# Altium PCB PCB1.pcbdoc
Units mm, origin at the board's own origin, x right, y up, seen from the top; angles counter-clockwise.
Board outline 128.65 x 93 mm, 2 copper layers (Top Layer, Bottom Layer), stack 1.58 mm thick; 4 components, 0 nets, 0 pads, 0 vias.
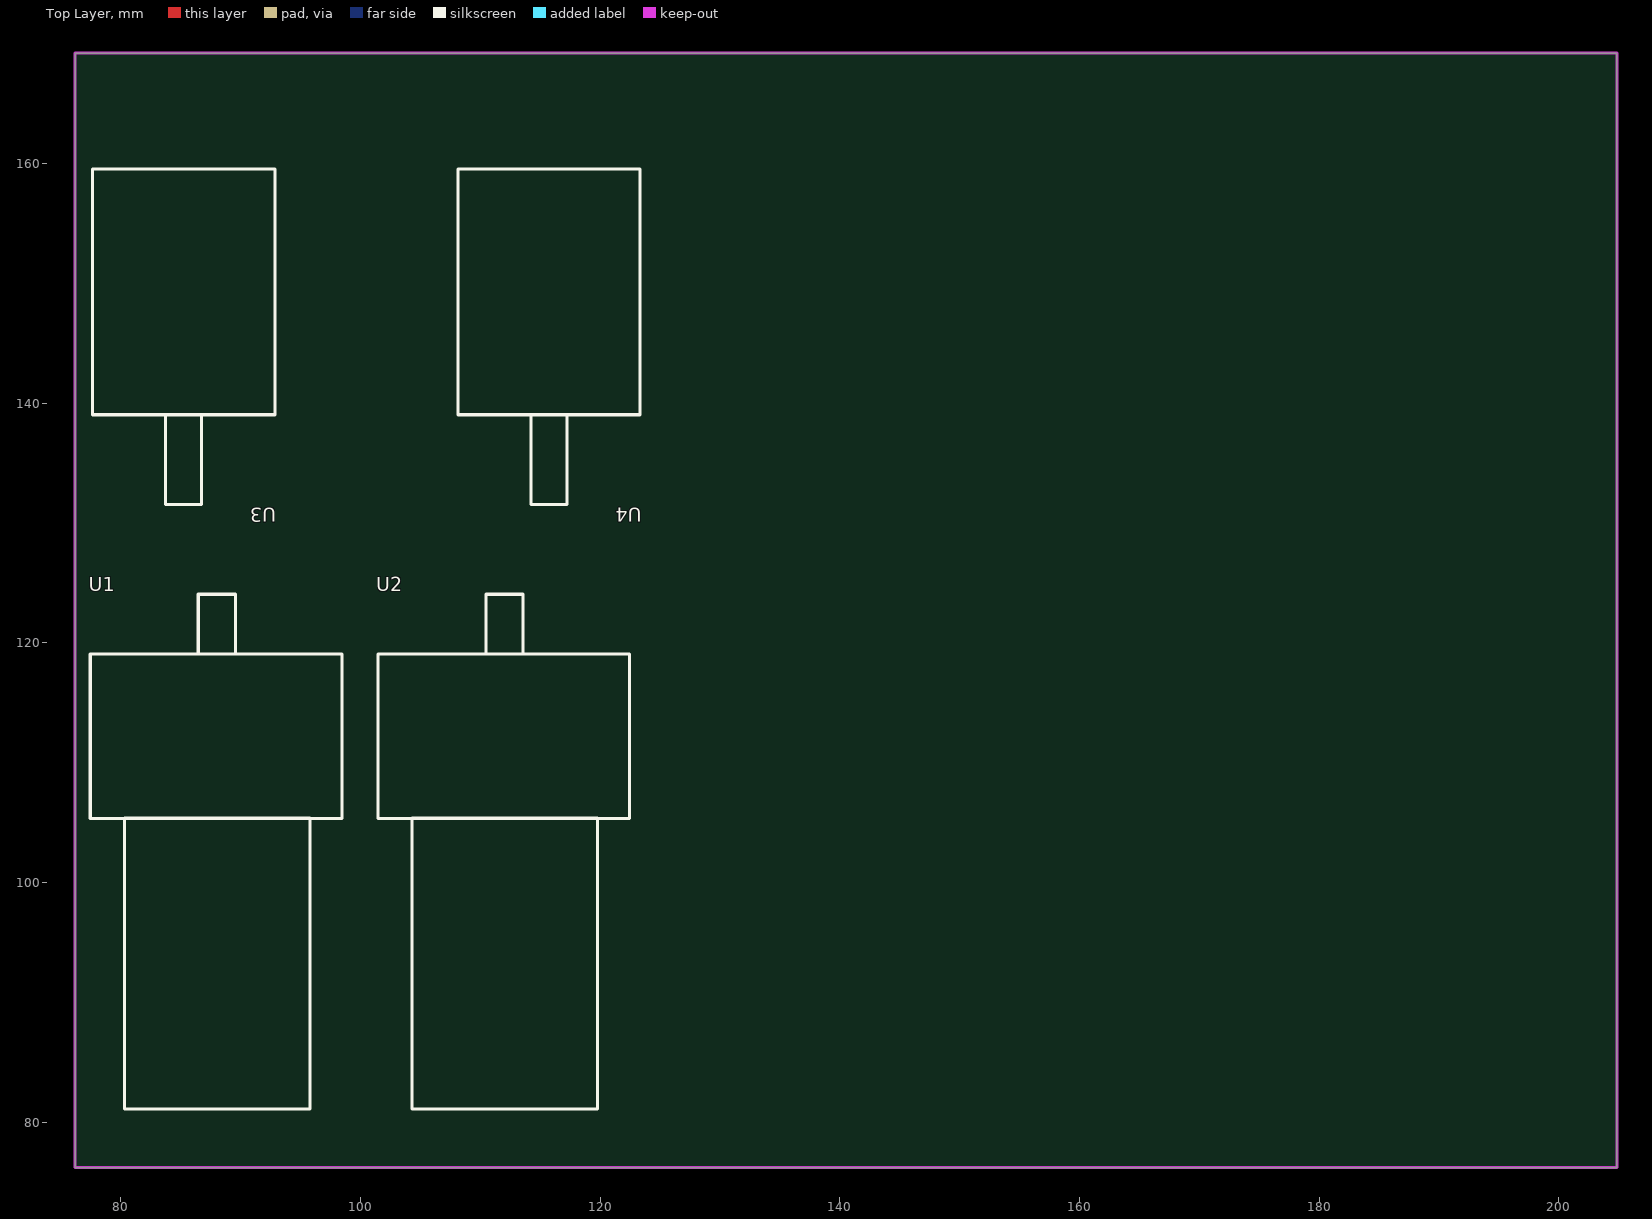
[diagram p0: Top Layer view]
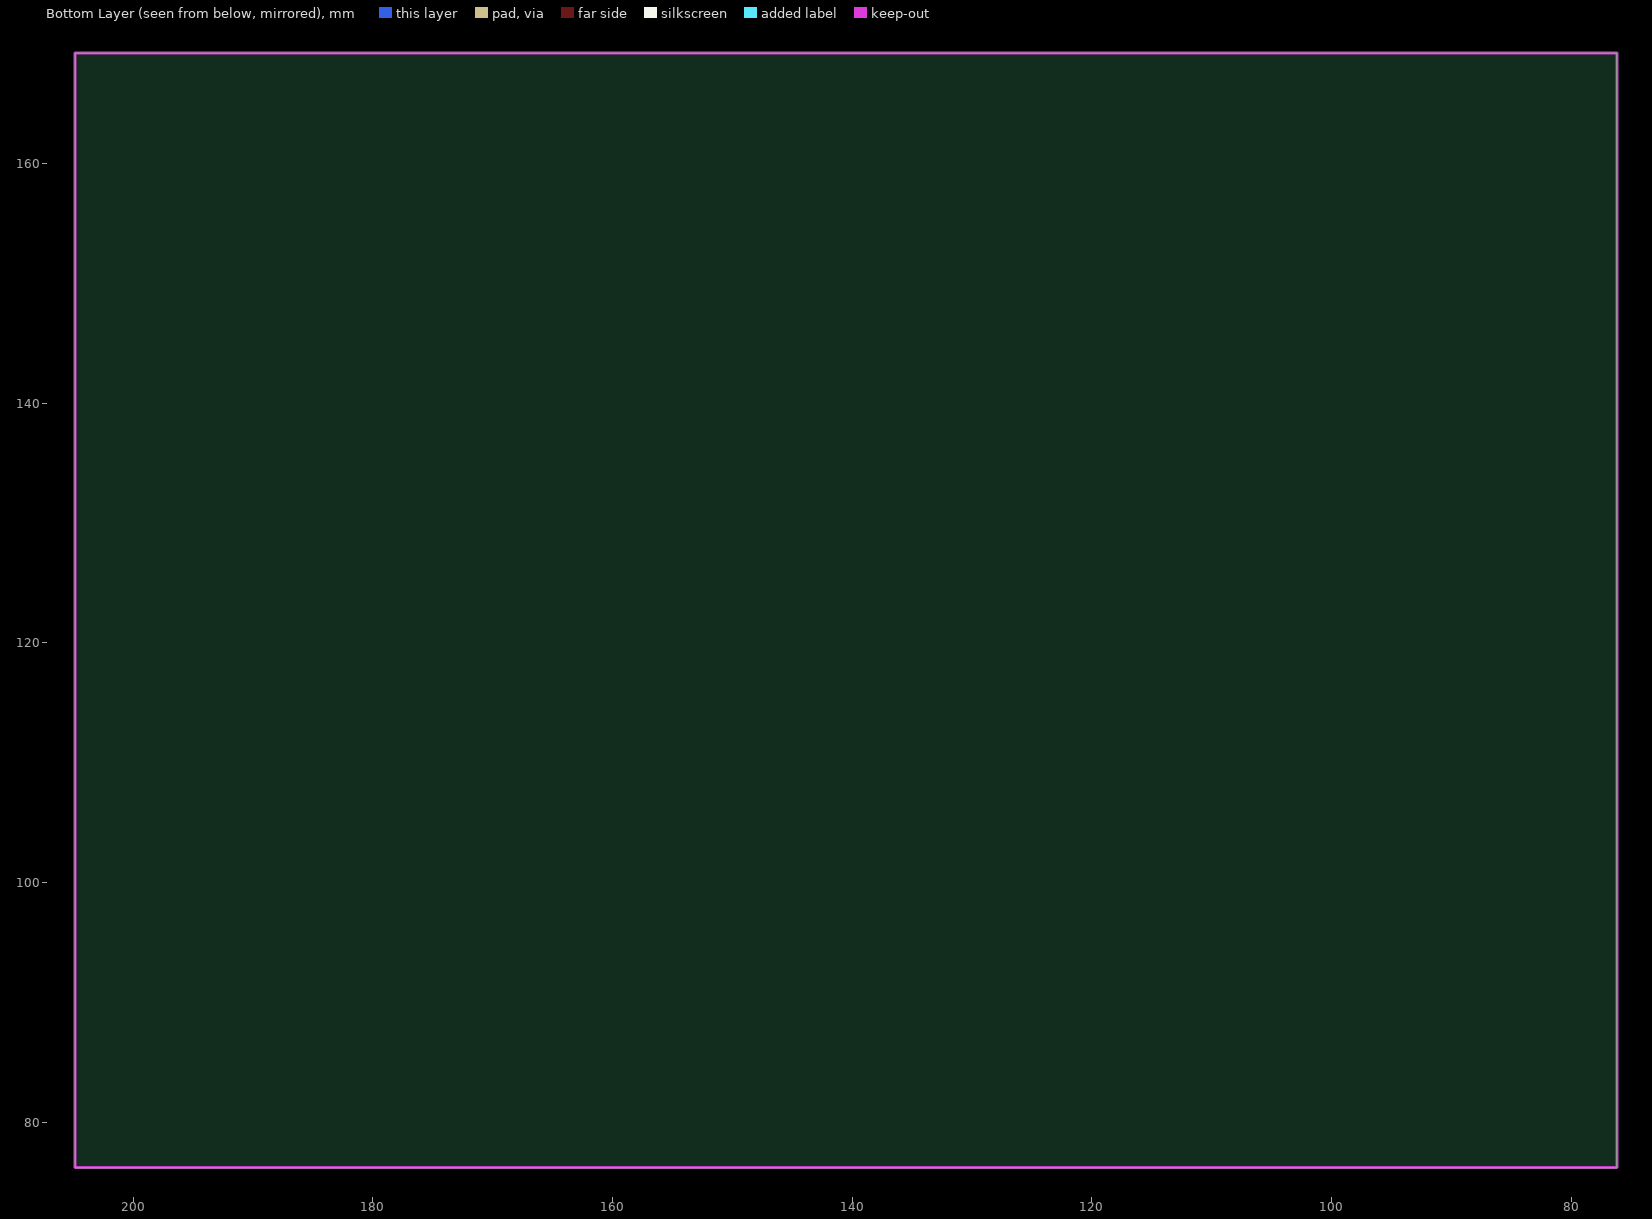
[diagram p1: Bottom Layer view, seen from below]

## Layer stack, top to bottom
Top Solder Mask Layer: solder mask 0.0102, Dk 3.3
Top Layer: signal copper 0.0356
Dielectric1: surface 1.5088, FR4, Dk 4.5
Bottom Layer: signal copper 0.0356
Bottom Solder Mask Layer: solder mask 0.0102, Dk 3.3

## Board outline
76.2,169.2 204.851,169.2 204.851,76.2 76.2,76.2

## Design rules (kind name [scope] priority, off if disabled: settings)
BoardOutlineClearance copperThickness1oz [All] p0: genericclearance=0.254 ignorepadtopadclearanceinfootprint=FALSE except(0: Arc-SplitContinuation Track-SplitContinuation SMDPad-SplitContinuation THPad-SplitContinuation Via-SplitContinuation Fill-SplitContinuation Poly-SplitContinuation Region-SplitContinuation Text-SplitContinuation)
BoardOutlineClearance copperThickness2oz [All] p0: genericclearance=0.254 ignorepadtopadclearanceinfootprint=FALSE except(0: Arc-SplitContinuation Track-SplitContinuation SMDPad-SplitContinuation THPad-SplitContinuation Via-SplitContinuation Fill-SplitContinuation Poly-SplitContinuation Region-SplitContinuation Text-SplitContinuation)
BoardOutlineClearance otherClearance [All] p0: genericclearance=0.254 ignorepadtopadclearanceinfootprint=FALSE except(0: Arc-SplitContinuation Track-SplitContinuation SMDPad-SplitContinuation THPad-SplitContinuation Via-SplitContinuation Fill-SplitContinuation Poly-SplitContinuation Region-SplitContinuation Text-SplitContinuation)
Clearance copperThickness1oz [All] p1: gap=0.178 ignorepadtopadclearanceinfootprint=FALSE
Clearance copperThickness2oz [All] p1: gap=0.178 ignorepadtopadclearanceinfootprint=FALSE
Clearance otherClearance [All] p1: gap=0.178 ignorepadtopadclearanceinfootprint=FALSE
DiffPairsRouting differentialPair [All] p1: maxuncoupledlength=10 minlimit=6 maxlimit=Infinity mostfreqgap=6 toplayer_minwidth=5 toplayer_prefwidth=10 toplayer_maxwidth=100 bottomlayer_minwidth=5 bottomlayer_prefwidth=10 bottomlayer_maxwidth=100
PasteMaskExpansion pasteMaskExpansion [All] p1: expansion=0
PlaneConnect innerPlane [All] p1: planeconnectstyle=Relief reliefexpansion=0.508 reliefentries=4 reliefconductorwidth=0.254 reliefairgap=0.254
PolygonConnect copperRegion [All] p1: connectstyle=Relief reliefentries=4 reliefconductorwidth=10 polygonreliefangle="90 Angle" airgapwidth=10
RoutingVias viaSize [All] p1: viastyle="Through Hole" holewidth=12.0078 minholewidth=11.811 maxholewidth=248.0314 width=12.0078 minwidth=11.811 maxwidth=248.0314
SolderMaskExpansion solderMaskExpansion [IsVia] p1: useseparateexpansions=TRUE expansion=-1000 expansionbottom=-1000
SolderMaskExpansion solderMaskExpansion [All] p2: useseparateexpansions=TRUE expansion=2 expansionbottom=2
Width copperThickness1oz [All] p1: maxlimit=100 minlimit=5 preferedwidth=10
Width copperThickness2oz [All] p1: maxlimit=100 minlimit=8 preferedwidth=10

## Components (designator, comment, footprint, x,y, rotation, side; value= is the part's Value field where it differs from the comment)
U1 "" JQB1523 88.049,105.372 r0 top
U2 "" JQB1523 112.052,105.372 r0 top
U3 "" 电磁阀 85.255,139.027 r180 top
U4 "" 电磁阀 115.735,139.027 r180 top

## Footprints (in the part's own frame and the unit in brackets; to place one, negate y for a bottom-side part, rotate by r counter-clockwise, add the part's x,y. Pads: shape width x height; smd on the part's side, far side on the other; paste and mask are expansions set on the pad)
JQB1523 [mm]
  silkscreen extent -10.59,-24.3 10.4,18.67
电磁阀 [mm]
  silkscreen extent -7.6,-20.5 7.6,7.5

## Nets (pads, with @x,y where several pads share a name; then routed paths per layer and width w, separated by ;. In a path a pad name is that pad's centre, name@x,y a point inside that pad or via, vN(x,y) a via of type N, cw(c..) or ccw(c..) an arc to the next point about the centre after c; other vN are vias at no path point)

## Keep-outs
Board Outline Layer:
  the board outline again, w0.254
